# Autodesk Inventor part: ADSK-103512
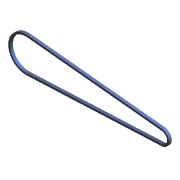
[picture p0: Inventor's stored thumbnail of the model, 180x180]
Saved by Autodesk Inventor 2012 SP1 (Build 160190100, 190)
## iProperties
Shininess: 0.0
Created: 2000-11
Part Number: ADSK-103512
Description: Roller Chain 60 x 140" LONG
Document SubType Name: Modeling
Designer: gao
Stock Number: ADSK-103512
Density: 1 g/cm^3
Material: Default
Density: 0.0
Volumn: 0.0
Area: 0.0
PropertySet Name: Model Information
Control State: 0
Master: False
Checked Out: False
Author: gao
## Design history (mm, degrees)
node "Extrusion1" dims "d4" = 25.4, "d5" = 0
  sketch "Sketch1"
    geometry: L1 (-36.607, -133.97)-(1193.809, -77.855); L2 (-28.61, 151.3)-(1196.73, 26.342); L3 (1198.479, 43.5)-(-26.86, 168.457); L4 (-35.821, -151.199)-(1194.595, -95.083); A1 r 143.078 centre (-43.125, 8.96) between (-28.61, 151.3) and (-36.607, -133.97); A2 r 52.261 centre (1191.428, -25.649) between (1193.809, -77.855) and (1196.73, 26.342); A3 r 160.325 centre (-43.125, 8.96) between (-26.86, 168.457) and (-35.821, -151.199); A4 r 69.507 centre (1191.428, -25.649) between (1194.595, -95.083) and (1198.479, 43.5)
    constraints: 8 end point, 8 point on circle, 8 tangent, 4 centre point, 3 other
    dimensions: "d1" = 286.1564 diameter of A1; "d2" = 104.521 diameter of A2; "d3" = 17.2466 distance between parallel lines of L3 L2
workplane "Work Plane1"
sketch "Sketch2"
  geometry: L1 (36.607, -133.97)-(-1193.809, -77.855) reference; L2 (-1196.73, 26.342)-(28.61, 151.3) reference; L3 (-1198.479, 43.5)-(26.86, 168.457) reference; L4 (35.821, -151.199)-(-1194.595, -95.083) reference; C1 r 685.8 at (43.125, 8.96); C2 r 647.7 at (43.125, 8.96); A1 r 143.078 centre (43.125, 8.96) between (36.607, -133.97) and (28.61, 151.3) reference; A2 r 52.261 centre (-1191.428, -25.649) between (-1196.73, 26.342) and (-1193.809, -77.855) reference; A3 r 69.507 centre (-1191.428, -25.649) between (-1198.479, 43.5) and (-1194.595, -95.083) reference; A4 r 160.325 centre (43.125, 8.96) between (35.821, -151.199) and (26.86, 168.457) reference; A5 r 685.8 centre (43.125, 8.96) between (685.454, 249.241) and (517.893, 503.851) reference; A6 r 114.3 centre (-402.442, -284.273) between (-506.98, -238.052) and (-497.851, -221.331) reference
  constraints: 2 centre point, 1 coincident, 1 concentric, 1 tangent
body "Solid1"
other parameters: "d6" = -14.4018
